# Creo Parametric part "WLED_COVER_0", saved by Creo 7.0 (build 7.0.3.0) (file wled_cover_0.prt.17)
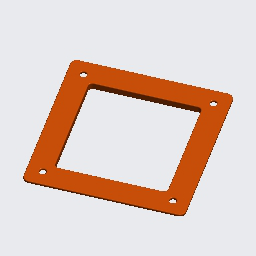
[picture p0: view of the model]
Units: millimeter Kilogram Sec (mmKs); MM, KILOGRAM, SECS

Created from: XX_SOLID_PART_MMKS_ABS.PRT

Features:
  1. coordinate system
  2. datum plane "RIGHT"
  3. datum plane "TOP"
  4. datum plane "FRONT"
  5. extrusion "Extrude 1"
  6. extruded cut "Extrude 2"
  7. extruded cut "Extrude 3"
  8. extruded cut "Extrude 4"
  9. round "Round 1"
  10. round "Round 2"
  11. round "Round 3"
  12. round "Round 4"
  13. chamfer "Chamfer 1"
  14. extruded cut "Extrude 5"
  15. round "Round 5"
  16. round "Round 6"

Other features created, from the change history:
  round "Round 5"
  extruded cut "Extrude 6"
  round "Round 7" (2 times)
  extruded cut "Extrude 7"
  extrusion "Extrude 8"
  extrusion "Extrude 9"
  round "Round 8"
  round "Round 9"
